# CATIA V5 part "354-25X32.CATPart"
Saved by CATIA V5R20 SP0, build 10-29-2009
Part number: 354-25X32
Definition: NONE
Nomenclature: 354-25X32
Source: Unknown
Description: 354-25X32
Bounding box of the stored display mesh (mm): x -16 to 16, y -19 to 19, z -19 to 19
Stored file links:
  C:\Users\Utente\Desktop\IO LAVORO\3D X SITO CF\X SITO\PLASTICA\354\354-25X32.CATPart
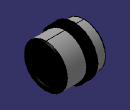
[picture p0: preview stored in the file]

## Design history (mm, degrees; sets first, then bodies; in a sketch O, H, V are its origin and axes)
Body1 "354-25X32" (main body)
  Solid1: solid without history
